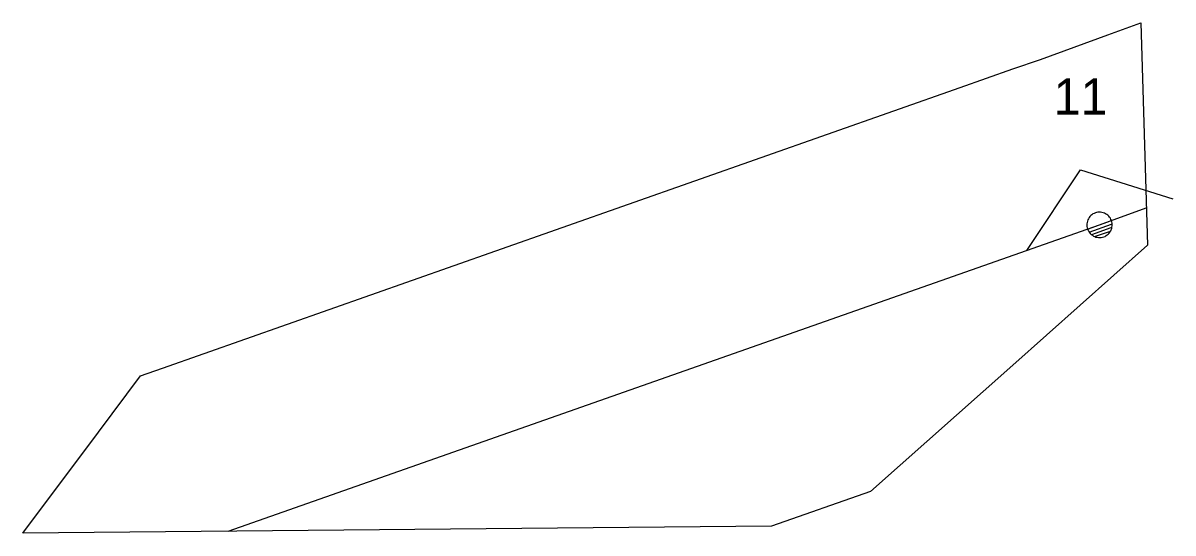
# Model space of a CAD drawing. Extents: x -544790 to -541580, y -1198998 to -1195432.
# Drawn here: x -541635.4 to -541579.8, y -1198986.6 to -1198961.9 of the extents above; entities that cross this region are included whole.
import ezdxf

# ---------------------------------------------------------------- set-up
doc = ezdxf.new("R2010")
doc.units = 0
for name, color, linetype in [('DOPLŇ_POPISY', 7, 'Continuous'), ('ELE_EON_POPIS', 7, 'Continuous'), ('KN_HRAN_POHYBLIVÁ', 7, 'Continuous'), ('PK_HRAN_SPORNÁ', 7, 'Continuous'), ('PLG_EXPORT_GPE', 7, 'Continuous'), ('PODZEM_NN_POPIS', 7, 'Continuous'), ('RÁMEČEK', 7, 'Continuous')]:
    doc.layers.add(name, color=color, linetype=linetype)

# ---------------------------------------------------------------- blocks, each defined once
blk = doc.blocks.new('VN860')
at = {"layer": 'RÁMEČEK'}
for points in [[(-3.738, 0.001), (0.012, 2.82)], [(0.012, 2.82), (3.762, 0.001)]]:
    blk.add_lwpolyline(points, dxfattribs=at)
blk = doc.blocks.new('VN440')
at = {"layer": 'ELE_EON_POPIS'}
for points in [[(1.22, 0), (1.21, 0.13), (1.19, 0.25), (1.16, 0.38), (1.11, 0.5), (1.05, 0.61), (0.98, 0.72), (0.9, 0.82), (0.81, 0.91), (0.71, 0.99), (0.6, 1.06), (0.49, 1.12), (0.37, 1.16), (0.25, 1.2), (0.12, 1.22), (-0.01, 1.22), (-0.14, 1.22), (-0.26, 1.2), (-0.39, 1.16), (-0.51, 1.12), (-0.62, 1.06), (-0.73, 0.99), (-0.83, 0.91), (-0.92, 0.82), (-1, 0.72), (-1.07, 0.61), (-1.13, 0.5), (-1.18, 0.38), (-1.21, 0.25), (-1.23, 0.13), (-1.24, 0), (-1.23, -0.13), (-1.21, -0.26), (-1.18, -0.38), (-1.13, -0.5), (-1.07, -0.62), (-1, -0.73), (-0.92, -0.83), (-0.83, -0.92), (-0.73, -1), (-0.62, -1.07), (-0.51, -1.13), (-0.39, -1.17), (-0.26, -1.2), (-0.14, -1.23), (-0.01, -1.23), (0.12, -1.23), (0.25, -1.2), (0.37, -1.17), (0.49, -1.13), (0.6, -1.07), (0.71, -1), (0.81, -0.92), (0.9, -0.83), (0.98, -0.73), (1.05, -0.62), (1.11, -0.5), (1.16, -0.38), (1.19, -0.26), (1.21, -0.13), (1.22, 0)], [(-1.24, 0), (1.22, 0)], [(-1.18, -0.34), (1.1, -0.34)], [(-1.01, -0.63), (0.97, -0.63)], [(-0.74, -0.92), (0.68, -0.92)]]:
    blk.add_lwpolyline(points, dxfattribs=at)

msp = doc.modelspace()

# ---------------------------------------------------------------- linework, layer by layer
at = {"layer": 'PK_HRAN_SPORNÁ'}
msp.add_lwpolyline([(-541581.304, -1198961.923), (-541580.991, -1198972.684), (-541587.5, -1198978.48), (-541594.379, -1198984.599), (-541599.167, -1198986.285), (-541635.375, -1198986.61), (-541631.73, -1198981.73), (-541629.687, -1198979), (-541628.63, -1198978.63), (-541612.5, -1198972.95), (-541590.05, -1198965.05), (-541587.5, -1198964.15), (-541586.156, -1198963.684), (-541582.9, -1198962.5)], close=True, dxfattribs=at)
at = {"layer": 'PODZEM_NN_POPIS'}
msp.add_lwpolyline([(-541625.451, -1198986.52), (-541583.3, -1198971.69), (-541581.044, -1198970.874)], dxfattribs=at)

# ---------------------------------------------------------------- block references
at = {"layer": 'DOPLŇ_POPISY', "xscale": 0.5, "yscale": 0.49999999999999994, "rotation": 19.38446122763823}
msp.add_blockref('VN440', (-541583.301, -1198971.69), dxfattribs=at)
at = {"layer": 'KN_HRAN_POHYBLIVÁ', "rotation": 19.38438607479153}
msp.add_blockref('VN860', (-541583.301, -1198971.69), dxfattribs=at)

# ---------------------------------------------------------------- texts
at = {"layer": 'PLG_EXPORT_GPE'}
msp.add_text('11', height=1.75, dxfattribs=at).set_placement((-541585.524, -1198966.36))

doc.saveas('drawing.dxf')
